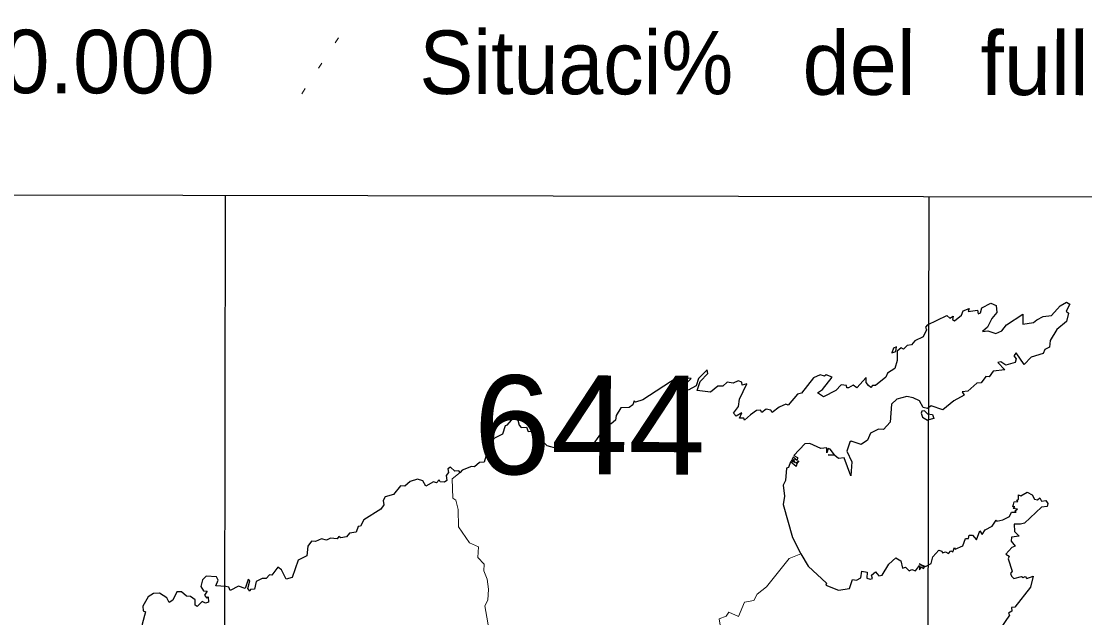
# Model space of a CAD drawing. Extents: x 483855 to 488461, y 4388206 to 4391419.
# Drawn here: x 488081.5 to 488290.9, y 4390464 to 4390581.6 of the extents above; entities that cross this region are included whole.
import ezdxf
from ezdxf.enums import TextEntityAlignment as Align

# ---------------------------------------------------------------- set-up
doc = ezdxf.new("R2010")
doc.units = 0
doc.header["$LTSCALE"] = 4
doc.linetypes.add('DOTTED', pattern=[1.5, 0.3, -1.2])
for name, color, linetype, lineweight in [('1', 7, 'Continuous', 13), ('2', 7, 'DOTTED', 13), ('3', 7, 'Continuous', 25)]:
    doc.layers.add(name, color=color, linetype=linetype, lineweight=lineweight)

msp = doc.modelspace()

# ---------------------------------------------------------------- linework, layer by layer
at = {"layer": '1', "lineweight": 25}
for p, q in [((487983.15, 4390547.59), (488398.83, 4390546.8)), ((488120.68, 4390005.39), (488121.71, 4390547.34)), ((488259.24, 4390005.13), (488260.27, 4390547.08))]:
    msp.add_line(p, q, dxfattribs=at)
at = {"layer": '2'}
msp.add_line((488136.7, 4390567.31), (488146.05, 4390581.59), dxfattribs=at)
at = {"layer": '3'}
for points in [[(488259.98, 4390521.74), (488263.74, 4390523.61), (488264.38, 4390523.08), (488265.01, 4390523.49), (488264.87, 4390522.79), (488265.29, 4390522.53), (488266.62, 4390523.69), (488266.95, 4390524.54), (488268.14, 4390524.96), (488267.97, 4390524.4), (488269.82, 4390524.68), (488269.94, 4390523.92), (488270.38, 4390524.15), (488270.66, 4390525.09), (488272.42, 4390526.05), (488273.48, 4390525.54), (488273.62, 4390524.16), (488272.62, 4390523)], [(488281.52, 4390522.76), (488282.72, 4390523.38), (488284.4, 4390523.59), (488286.06, 4390525.51), (488287.33, 4390526.25), (488287.99, 4390525.83), (488287.27, 4390524.47), (488287.74, 4390524.04), (488287.31, 4390522.43), (488285.46, 4390520.86), (488284.1, 4390518.65), (488283.96, 4390517.39), (488283.07, 4390516.89), (488282.74, 4390516.1)], [(488272.62, 4390523), (488271.77, 4390521.32), (488270.81, 4390520.47), (488271.86, 4390520.57), (488273.4, 4390520.07), (488274.61, 4390520.6), (488275.52, 4390521.78), (488278.71, 4390523.89), (488278.76, 4390521.89), (488280.81, 4390522.21), (488281.52, 4390522.76)], [(488259.98, 4390521.74), (488259.55, 4390521.32), (488259.76, 4390520.77), (488259.09, 4390519.42), (488257.48, 4390518.63), (488256.81, 4390517.81), (488255.98, 4390517.69), (488255.26, 4390516.99), (488254.77, 4390517.24), (488253.98, 4390516.54), (488253.99, 4390514.71), (488253.5, 4390513.16), (488252.06, 4390512.21), (488251.74, 4390511.47), (488249.7, 4390509.77), (488249.09, 4390509.79), (488248.79, 4390509.39), (488248.33, 4390509.77)], [(488282.74, 4390516.1), (488280.38, 4390515.38), (488278.97, 4390513.96), (488277.44, 4390516.22), (488276.94, 4390515.67), (488277.42, 4390515.09), (488277.25, 4390514.31), (488275.41, 4390513.78), (488274.37, 4390514.44), (488273.83, 4390514.33), (488275.16, 4390512.86), (488272.89, 4390512.62), (488272.1, 4390511.53), (488271.46, 4390511.55)], [(488218.63, 4390509.7), (488217.22, 4390508.48), (488214.59, 4390508.81), (488215.18, 4390510.59), (488216.68, 4390512.19), (488216.58, 4390512.89), (488214.83, 4390511.18), (488214.39, 4390509.76), (488212.82, 4390508.88), (488211.97, 4390509.27), (488211.94, 4390509.75), (488213.39, 4390511.2), (488211.37, 4390511.22)], [(488211.37, 4390511.22), (488210.66, 4390511.4), (488203.88, 4390507), (488202.45, 4390506.5), (488202.2, 4390506.79), (488201.95, 4390505.98), (488201.2, 4390505.45), (488199.58, 4390505.38), (488198.63, 4390503.92), (488198.52, 4390502.94), (488197.65, 4390502.23), (488196.68, 4390501.95)], [(488225.1, 4390504.01), (488223.9, 4390503), (488223.81, 4390503.34), (488222.9, 4390503.36), (488223.42, 4390504.42), (488222.28, 4390503.74), (488221.75, 4390504.37), (488222.7, 4390505.64), (488222.96, 4390507.14), (488224.4, 4390510.11), (488223.47, 4390509.87), (488223.38, 4390510.43), (488222.68, 4390510.72), (488221.7, 4390510.28), (488220.52, 4390510.46), (488219.62, 4390509.69), (488218.63, 4390509.7)], [(488239.65, 4390511.63), (488238.79, 4390511.93), (488237.5, 4390511.31), (488235.14, 4390508.29), (488234.37, 4390508.12), (488232.5, 4390505.93), (488232.04, 4390506.12), (488230.74, 4390505.55), (488229.37, 4390504.46), (488229.07, 4390504.97), (488228.2, 4390505.12), (488227.34, 4390504.5), (488227.08, 4390504.92), (488226.3, 4390504.88), (488225.1, 4390504.01)], [(488248.33, 4390509.77), (488247.88, 4390510.4), (488247.89, 4390511.41), (488246.05, 4390509.32), (488245.33, 4390509.88), (488244.42, 4390509.33), (488244.04, 4390509.36), (488243.99, 4390509.81), (488242.94, 4390509.91), (488241.88, 4390508.8), (488239.44, 4390507.55), (488238.29, 4390508.35), (488239.29, 4390509.01), (488241.15, 4390511.45), (488239.97, 4390511.89), (488239.65, 4390511.63)], [(488271.46, 4390511.55), (488270.54, 4390510.33), (488269.69, 4390510.27), (488267.88, 4390508.66), (488266.81, 4390508.55), (488267.17, 4390507.91), (488265.16, 4390506.81), (488263, 4390504.98), (488260.71, 4390505.78), (488259.97, 4390505.29)], [(488259.97, 4390505.29), (488259.09, 4390505.45), (488258.37, 4390506.75), (488257.14, 4390507.39), (488255.91, 4390507.65), (488253.9, 4390507.13), (488252.86, 4390506.13), (488252.63, 4390502.57), (488251.93, 4390501.87)], [(488259.97, 4390504.25), (488259.39, 4390504.84), (488258.81, 4390504.75), (488258.69, 4390504.34), (488258.95, 4390503.55), (488259.98, 4390502.94)], [(488177.15, 4390501.99), (488178.49, 4390503.47), (488179.27, 4390502.96), (488179.53, 4390501.99)], [(488259.97, 4390504.25), (488260.91, 4390504.06), (488261.22, 4390503.28), (488259.98, 4390502.94)], [(488177.15, 4390501.99), (488176.75, 4390501.84), (488176.25, 4390500.19), (488174.53, 4390499.36), (488173.5, 4390497.59), (488172.61, 4390494.72), (488171.73, 4390494.63), (488170.72, 4390493.74), (488170.12, 4390493.86), (488168.29, 4390493.14), (488167.9, 4390492.66)], [(488179.53, 4390501.99), (488179.95, 4390501.5), (488180.95, 4390501.62), (488181.31, 4390500.71), (488182.37, 4390500.89), (488183.04, 4390500.15), (488183.99, 4390500.39), (488183.59, 4390499.31), (488184.99, 4390497.98), (488186.91, 4390497.45), (488187.99, 4390498.2), (488188.57, 4390497.98), (488188.76, 4390497.36), (488189.18, 4390497.7), (488189.63, 4390497.29), (488190.94, 4390497.64)], [(488196.68, 4390501.95), (488196.48, 4390500.53), (488195.7, 4390500.48), (488193.63, 4390497.56), (488192.81, 4390497.31), (488192.41, 4390497.6), (488192.06, 4390497.15), (488190.94, 4390497.64)], [(488251.93, 4390501.87), (488251.26, 4390501.16), (488250.33, 4390501.19), (488248.71, 4390500.41), (488248.12, 4390499.02), (488246.89, 4390498.15), (488244.94, 4390498.82), (488244.64, 4390498.62), (488244.08, 4390496.86), (488245.06, 4390494.77), (488244.83, 4390491.98), (488243.55, 4390495.57), (488242.4, 4390495.39), (488241.71, 4390496.01), (488240.4, 4390496.14)], [(488240.4, 4390496.14), (488241.67, 4390496.14), (488240.81, 4390497.23), (488240.4, 4390497.39), (488240.1, 4390496.55), (488240.12, 4390497.52), (488238.96, 4390497.36), (488236.81, 4390498.4), (488235.78, 4390498.33), (488233.61, 4390496.03), (488234.32, 4390495.59), (488234.26, 4390495.05), (488233.5, 4390495.71), (488233.29, 4390495.27), (488233.83, 4390495.08), (488233.19, 4390495.11), (488233.82, 4390494.78), (488233.08, 4390494.94), (488234.12, 4390494.56), (488234.63, 4390494.93), (488234.25, 4390494.45)], [(488234.25, 4390494.45), (488234.09, 4390493.87), (488232.97, 4390494.74), (488232.59, 4390493.61), (488232.18, 4390493.51), (488232.02, 4390491.05), (488231.51, 4390490.16), (488231.81, 4390488.02), (488231.5, 4390486.33), (488233.38, 4390479.86), (488235.03, 4390476.65)], [(488167.9, 4390492.66), (488167.65, 4390492.98), (488166.87, 4390492.91), (488165.99, 4390493.72), (488165.51, 4390493.35), (488165.59, 4390492.68), (488165.13, 4390492.05), (488165.29, 4390491.07), (488164.82, 4390490.78), (488163.97, 4390490.84), (488163.8, 4390491.21), (488163.26, 4390490.61), (488162.69, 4390490.81), (488161.13, 4390489.99), (488160.56, 4390491.02), (488159.49, 4390491.37), (488158.04, 4390490.88), (488157, 4390489.93), (488156.16, 4390490.01)], [(488156.16, 4390490.01), (488154.78, 4390488.31), (488153.13, 4390487.84), (488152.73, 4390487.12), (488152.9, 4390486.27), (488152.26, 4390485.45), (488148.94, 4390483.35), (488148.3, 4390482.06), (488147.8, 4390481.99), (488147.44, 4390480.87)], [(488276.9, 4390486.33), (488277.04, 4390486.88), (488277.76, 4390486.96), (488277.52, 4390487.27), (488277.87, 4390487.34), (488277.86, 4390488.23), (488278.31, 4390488.05), (488279.61, 4390488.75), (488280.59, 4390488.24), (488281.05, 4390487.42), (488281.62, 4390487.29), (488282.05, 4390487.66), (488282.41, 4390487), (488283.27, 4390487.17), (488283.63, 4390486.53), (488283.5, 4390485.96), (488282.43, 4390485.83), (488279.03, 4390482.64), (488278.27, 4390482.46)], [(488269.6, 4390479.41), (488270.24, 4390481.13), (488270.72, 4390480.41), (488271.32, 4390481.35), (488272.68, 4390482.06), (488273.51, 4390483.29), (488273.63, 4390483.04), (488274.8, 4390483.3), (488276.12, 4390484), (488276.52, 4390484.82), (488277.44, 4390484.87), (488277.17, 4390485.09), (488277.69, 4390485.43), (488276.84, 4390485.56), (488277.17, 4390485.87), (488276.75, 4390485.92), (488276.9, 4390486.33)], [(488278.27, 4390482.46), (488277, 4390482.45), (488277.12, 4390481.06), (488277.99, 4390480.09), (488276.49, 4390479.92), (488276.42, 4390479.14), (488277.2, 4390478.11), (488276.54, 4390477.89), (488275.36, 4390476.59), (488276.07, 4390476.16), (488275.84, 4390475.61), (488276.66, 4390473.21), (488276.33, 4390472.78), (488276.52, 4390472.25), (488276.94, 4390471.79), (488278.46, 4390472.19), (488278.78, 4390471.94), (488279.19, 4390472.18), (488279.54, 4390471.78)], [(488147.44, 4390480.87), (488146.14, 4390480.67), (488145.55, 4390479.96), (488144.38, 4390479.79), (488144.04, 4390480.06), (488143.71, 4390479.56), (488142.4, 4390479.74), (488141.6, 4390479.3), (488140.61, 4390479.58), (488139.44, 4390479.05), (488138.64, 4390479.13), (488137.93, 4390478.12), (488137.74, 4390476.24), (488136.03, 4390475.37), (488134.81, 4390471.95), (488133.67, 4390471.62), (488132.73, 4390473.49)], [(488259.96, 4390474.35), (488260.69, 4390474.69), (488261.02, 4390476.05), (488262.16, 4390477.32), (488262.81, 4390477.17), (488262.91, 4390476.81), (488263.52, 4390477.01), (488264.09, 4390476.68), (488264.56, 4390477.22), (488264.96, 4390477.04), (488265.27, 4390477.86), (488265.42, 4390477.57), (488266.92, 4390478.22), (488267.46, 4390479.64), (488268.04, 4390479.66), (488268.16, 4390480.3), (488268.85, 4390480.3), (488269.6, 4390479.41)], [(488235.03, 4390476.65), (488236.42, 4390474.2), (488240.05, 4390470.82), (488239.96, 4390470.47), (488242.44, 4390469.46), (488244.57, 4390469.8), (488245.2, 4390471.54), (488245.99, 4390471.42), (488246.84, 4390471.88), (488246.99, 4390473.2), (488248.07, 4390472.99), (488248.01, 4390471.81), (488248.66, 4390471.64), (488249.1, 4390471.77), (488248.94, 4390472.44), (488249.71, 4390473.06)], [(488249.71, 4390473.06), (488250.37, 4390472.3), (488251, 4390472.42), (488252.32, 4390474.59), (488253.75, 4390475.84), (488254.69, 4390475.25), (488255.05, 4390473.78), (488255.64, 4390474.02), (488256.32, 4390473.26), (488256.86, 4390473.52), (488257.61, 4390473.25), (488258.4, 4390474.3), (488258.39, 4390473.47), (488258.78, 4390474.08), (488259.14, 4390473.74), (488259.34, 4390473.99), (488258.34, 4390474.67), (488259.54, 4390474.16), (488259.96, 4390474.35)], [(488132.73, 4390473.49), (488131.99, 4390474.03), (488130.8, 4390472.43), (488130.33, 4390472.52), (488129.71, 4390471.76), (488128.89, 4390471.79), (488127.73, 4390471.18), (488127.38, 4390469.67), (488126.65, 4390469.61), (488126.48, 4390469.25), (488126.12, 4390469.82), (488126.5, 4390471.29), (488126.15, 4390471.56), (488125.55, 4390469.77), (488124.23, 4390470.25), (488122.64, 4390469.42), (488122.34, 4390470.04), (488121.78, 4390470.18)], [(488121.78, 4390470.18), (488119.78, 4390470.34), (488120.25, 4390471.43), (488119.89, 4390472.11), (488117.89, 4390472.23), (488117.17, 4390471.51), (488116.83, 4390470.22), (488117.35, 4390469.36), (488118.06, 4390469.25), (488117.56, 4390468.47), (488117.94, 4390467.95), (488118.27, 4390468.14), (488118.37, 4390467.1), (488117.75, 4390466.93), (488117.08, 4390467.26), (488116.11, 4390466.22), (488115.74, 4390466.51), (488115.71, 4390467.56), (488114.8, 4390468.24), (488114.03, 4390468.28), (488113.06, 4390469.14)], [(488279.54, 4390471.78), (488280.78, 4390472.24), (488280.22, 4390470.08), (488277.18, 4390466.13), (488276.53, 4390466.06), (488276.54, 4390465.32), (488275.94, 4390464.96), (488276.1, 4390464.56), (488274.25, 4390461.82), (488273.12, 4390460.89), (488273.07, 4390460.27), (488272.37, 4390460.43), (488271.63, 4390460.08), (488270.94, 4390458.85), (488269.61, 4390458.82), (488268.98, 4390458.36), (488268.12, 4390458.98)], [(488113.06, 4390469.14), (488112.12, 4390469.16), (488111.35, 4390467.47), (488110.59, 4390467.04), (488110.14, 4390467.95), (488108.67, 4390468.88), (488107.54, 4390468.84), (488106.49, 4390468.12), (488105.4, 4390466.31), (488105.51, 4390465.41), (488105.96, 4390465.18), (488105.27, 4390462.76), (488105.38, 4390461.72), (488106.21, 4390460.22), (488103.73, 4390460.57), (488102.78, 4390461.66)]]:
    msp.add_lwpolyline(points, dxfattribs=at)
msp.add_lwpolyline([(488253.85, 4390517.44), (488253.23, 4390517.14), (488252.96, 4390516.27), (488253.69, 4390516.48)], close=True, dxfattribs=at)
at = {"layer": '3', "lineweight": 13}
for points in [[(488167.9, 4390492.66), (488166.33, 4390491.39), (488166.49, 4390487.61), (488167.04, 4390487.18), (488167.53, 4390485.37), (488167.59, 4390481.98), (488169.76, 4390478.77), (488171.54, 4390478.03), (488171.4, 4390475.92), (488172.61, 4390474.56), (488172.56, 4390473.25), (488173.26, 4390471.65), (488173.51, 4390469.67), (488173.36, 4390467.5), (488172.78, 4390466.35), (488173.81, 4390460.38), (488174.45, 4390458.63), (488175.7, 4390456.84)], [(488235.03, 4390476.65), (488232.72, 4390475.71), (488228.22, 4390470.1), (488226.42, 4390468.66), (488225.72, 4390467.45), (488223.93, 4390467.09), (488222.75, 4390464.27), (488220.82, 4390465.15), (488220.32, 4390464.31), (488218.9, 4390463.8), (488219.43, 4390460.48), (488218.94, 4390458.98), (488219.49, 4390456.75)]]:
    msp.add_lwpolyline(points, dxfattribs=at)

# ---------------------------------------------------------------- texts
at = {"layer": '2'}
for s, p in [('1:50.000', (488054.49, 4390567.47)), ('del', (488235.33, 4390567.12)), ('full', (488270.34, 4390567.06))]:
    msp.add_text(s, height=12.5, rotation=359.891, dxfattribs=at).set_placement(p)
at = {"layer": '2', "width": 0.95}
msp.add_text('Situaci%', height=12.5, rotation=359.891, dxfattribs=at).set_placement((488159.89, 4390567.27))
at = {"layer": '2', "width": 1.05}
msp.add_text('644', height=19.5, rotation=359.891, dxfattribs=at).set_placement((488193.39, 4390492.28), align=Align.CENTER)

doc.saveas('drawing.dxf')
